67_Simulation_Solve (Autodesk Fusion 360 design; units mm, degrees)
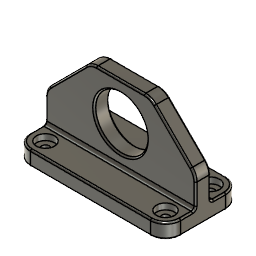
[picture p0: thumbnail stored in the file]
part number: 2026-07-20-13-25-26-316
sketch "Sketch1" plane through (0, 0, 0) normal (0, 1, 0) x axis (1, 0, 0)
  line L1 (-50, 25) -> (50, 25)
  line L2 (-50, -25) -> (-50, 25)
  line L3 (50, -25) -> (-50, -25)
  line L4 (50, 25) -> (50, -25)
  line L5 (-50, -25) -> (50, 25)
  line L6 (50, -25) -> (-50, 25)
  point P6 (0, 0)
  point P1 (0, 0)
  point P4 (-50, -25)
  point P5 (50, -25)
  point P3 (-50, 25)
  horizontal L1
  perpendicular L1 L2
  parallel L1 L3
  parallel L2 L4
  coincident L5 P6
  coincident L6 P6
  coincident P1 P6
  dimension "d2" distance P4 P5 = 100
  dimension "d3" distance P3 P4 = 50
extrude "Extrude1" new body sketch "Sketch1" profile of L1 L2 L3 L4 distance 10
sketch "Sketch2" plane through (0, 0, -25) normal (0, 0, -1) x axis (1, 0, 0)
  line L1 (-50, -5) -> (-50, 5)
  line L2 (50, -5) -> (-50, -5)
  line L3 (50, 5) -> (50, -5)
  line L4 (-50, 5) -> (50, 5)
  line L5 (-50, -25) -> (50, -25)
  line L6 (-50, 25) -> (-50, -25)
  line L7 (50, 25) -> (-50, 25)
  line L8 (50, -25) -> (50, 25)
  line L9 (-50, 25) -> (50, -25)
  line L10 (50, 25) -> (-50, -25)
  point P10 (0, 0)
  point P1 (0, 0)
  point P5 (50, 5)
  point P7 (-50, -25)
  point P8 (-50, 25)
  horizontal L5
  perpendicular L5 L6
  parallel L5 L7
  parallel L6 L8
  coincident L9 P10
  coincident L10 P10
  coincident P1 P10
  coincident P5 L8
  dimension "d6" distance P7 P8 = 50
extrude "Extrude2" add sketch "Sketch2" profile of L1 L2 L3 L4 L5 L6 L7 L8 along normal blind 10
chamfer "Chamfer1" sketch "Sketch2" distance 30
sketch "Sketch3" plane through (0, -5, 0) normal (0, -1, 0) x axis (1, 0, 0)
  line L1 (20, 25) -> (50, -5)
  line L2 (-20, 25) -> (20, 25)
  line L3 (-50, -5) -> (-20, 25)
  line L4 (-50, -25) -> (-50, -5)
  line L5 (50, -25) -> (-50, -25)
  line L6 (50, -5) -> (50, -25)
  circle C1 centre (0, 0) radius 17.5
  point P1 (0, 0)
  point P8 (0, 0)
  coincident P1 P8
  dimension "d10" diameter C1 = 35
extrude "Extrude3" cut sketch "Sketch3" profile of C1 no distance stored
fillet "Fillet1" radius 10
fillet "Fillet2" radius 10
sketch "Sketch4" plane through (0, 0, -25) normal (0, 0, 1) x axis (-1, 0, 0)
  line L1 (50, -5) -> (50, -15)
  line L2 (-50, -5) -> (50, -5)
  line L3 (-50, -15) -> (-50, -5)
  line L4 (40, -25) -> (-40, -25)
  line L5 (-40, 25) -> (40, 25)
  line L6 (-50, 5) -> (-50, 15)
  line L7 (50, 5) -> (-50, 5)
  line L8 (50, 15) -> (50, 5)
  arc A1 centre (40, -15) radius 10 clockwise from (50, -15) to (40, -25)
  arc A2 centre (-40, -15) radius 10 clockwise from (-40, -25) to (-50, -15)
  arc A3 centre (40, 15) radius 10 clockwise from (40, 25) to (50, 15)
  arc A4 centre (-40, 15) radius 10 clockwise from (-50, 15) to (-40, 25)
  point P9 (-40, -15)
  point P18 (-40, -15)
  point P4 (40, -15)
  point P19 (40, -15)
  point P12 (40, 15)
  point P20 (40, 15)
  point P15 (-40, 15)
  point P21 (-40, 15)
  coincident P9 P18
  coincident P4 P19
  coincident P12 P20
  coincident P15 P21
hole "Hole1" sketch "Sketch2" HoleDiameter 5 TipAngle 118 CBDepth 4 CBDiameter 12
fillet "Fillet3" radius 2
fillet "Fillet4" radius 1
chamfer "Chamfer2" sketch "Sketch2" distance 1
